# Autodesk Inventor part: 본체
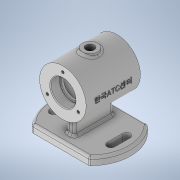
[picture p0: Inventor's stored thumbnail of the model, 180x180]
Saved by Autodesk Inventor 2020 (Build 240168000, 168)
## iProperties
Created: 2021-09
Part Number: 본체
Material: 일반
Document SubType Name: Modeling
Designer: Administrator
Density: 1 g/cm^3
Appearance: 기본값
Author: Administrator
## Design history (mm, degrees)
sketch "스케치1"
  geometry: L1 (-37.499, 0.259)-(37.499, -0.259); A1 r 52.5 centre (0, 0) between (37.752, 36.483) and (37.246, -37); 4 further points
  constraints: 4 point on circle, 2 coincident, 2 end point, 1 centre point, 1 midpoint
  dimensions: "d0" = 105 diameter of A1; "d66" = 37 vertical distance of point (-37.246, 37) point (0, 0)
extrude "돌출1" new body sketch "스케치1" stored distance "d2" = 10; taper "d3" = 0 deg
sketch "스케치2"
  geometry: L1 (35, 57)-(-35, 57); L2 (35, 57)-(35, 87); L3 (35, 87)-(-35, 87); L4 (-35, 87)-(-35, 57); 5 further points; 1 other entity
  constraints: 8 end point, 2 horizontal, 1 midpoint, 1 perpendicular, 1 vertical, 1 vertical alignment, 2 other
  dimensions: "d4" = 62 dimension on L1; "d5" = 70 distance of L1.start L1.end; "d6" = 60 diameter of L3 L1
revolve "회전1" sketch "스케치2" stored, may be unused: angle "d7" = 90 deg
revolve "회전2" stored, may be unused: angle "d19" = 90 deg
node "작업 평면1"
sketch "스케치6"
  geometry: L1 (-35, -30)-(-35, 30) reference; L2 (35, -30)-(35, 30) reference; C1 r 10 at (0, 0); 1 further point
  constraints: 1 centre point, 1 coincident
  dimensions: "d21" = 20 diameter of C1
extrude "돌출3" join sketch "스케치6" stored distance "d22" = 10; taper "d23" = 0 deg; dims "d12" = 32, "d13" = 28, "d14" = 50, "d15" = 12, "d17" = 40, "d18" = 12, "d24" = 10.917, "d26" = 4, "d27" = 2, "d29" = 29.1
sketch "스케치7"
  geometry: C1 r 10 at (0, 0) reference; 2 further points
  constraints: 1 coincident
hole "구멍1" sketch "스케치7" at (0, 0) diameter "d24" = 10.917; stored, may be unused: countersink angle "d28" = 90 deg, drill point angle "d30" = 118 deg; dims "d25" = 24, "d26" = 4, "d27" = 2, "d29" = 29.1
sketch "스케치8"
  geometry: L1 (-15, 37)-(15, 37); L2 (-10, 32)-(10, 32); L3 (10, 42)-(-10, 42); C1 r 52.5 at (0, 0) reference; A1 r 5 centre (-10, 37) between (-10, 42) and (-10, 32); A2 r 5 centre (10, 37) between (10, 32) and (10, 42); 3 further points
  constraints: 8 end point, 6 point on circle, 4 tangent, 2 centre point, 2 midpoint, 2 point on line, 1 horizontal, 1 parallel, 1 vertical alignment
  dimensions: "d31" = 20 distance of A2.centre A1.centre; "d32" = 37 distance of point (0, 0) point (0, 37); "d33" = 5 radius of A1
extrude "돌출4" cut sketch "스케치8" extent not by distance; stored distance "d34" = 0; taper "d35" = 0 deg
sketch "스케치9" dims "d36" = 46
  geometry: C1 r 16 at (0, 0) reference; 3 further points
  constraints: 1 coincident, 1 horizontal alignment, 2 other
hole "구멍2" sketch "스케치9" at (23, 0) diameter "d37" = 3.45873; stored, may be unused: countersink angle "d41" = 90 deg, drill point angle "d43" = 118 deg; dims "d38" = 8, "d39" = 4, "d40" = 2, "d42" = 10
fillet "모깎기1" dims "d47" = 0.3
fillet "모깎기2" dims "d48" = 3
fillet "모깎기3" dims "d49" = 3
chamfer "모따기1" distance "d52" = 1; stored, may be unused: second distance "d53" = 2, angle "d54" = 45 deg
node "작업 평면2"
sketch "스케치10"
  geometry: L1 (-35, 87)-(-35, 27) reference; L2 (35, 87)-(35, 27) reference; L3 (35, 87)-(-35, 87) reference; L4 (35, 27)-(-35, 27) reference; 2 further points
  constraints: 1 other
  dimensions: "d57" = 30 distance from line of L3 point (0, 57); "d58" = 35 distance from line of L1 point (0, 57)
feature "엠보싱1" sketch "스케치10" dims "d2" = 10, "d12" = 32, "d13" = 28, "d14" = 50, "d15" = 12, "d17" = 40, "d18" = 12, "d59" = 0.5, "d60" = 0
sketch "스케치11"
  geometry: L1 (15, -5)-(10, -5) reference; L2 (-52.5, -5)-(52.5, -5) reference; L3 (25, -5)-(-25, -5); L4 (-25, -5)-(-25, 29.906); L5 (-25, 29.906)-(25, 29.906); L6 (25, 29.906)-(25, -5); 4 further points
  constraints: 8 end point, 2 midpoint, 2 parallel, 1 horizontal, 1 perpendicular, 1 point on line, 1 vertical alignment
  dimensions: "d67" = 50 distance between parallel lines of L6 L4; "d68" = 34.90626 distance from line of L1.start L5
extrude "돌출5" join sketch "스케치11" stored distance "d69" = 10; taper "d70" = 0 deg
fillet "모깎기7" dims "d71" = 3
fillet "모깎기8" dims "d72" = 3
node "작업 평면3"
sketch "스케치13"
  geometry: L1 (10, -32)-(-10, -32) reference; L2 (-10, -42)-(10, -42) reference; L3 (10, 42)-(-10, 42) reference; L4 (-10, 32)-(10, 32) reference; L5 (-37.5, 36.742)-(-37.5, -36.742); L6 (37.5, 36.742)-(37.5, -36.742); L7 (0, 0)-(0, -52.5); C1 r 52.5 at (0, 0) reference; A1 r 5 centre (-10, -37) between (-10, -32) and (-10, -42) reference; A2 r 5 centre (10, -37) between (10, -42) and (10, -32) reference; A3 r 5 centre (-10, 37) between (-10, 42) and (-10, 32) reference; A4 r 5 centre (10, 37) between (10, 32) and (10, 42) reference; A5 r 52.5 centre (0, 0) between (-37.5, 36.742) and (-37.5, -36.742) reference; 5 further points
  constraints: 6 end point, 5 point on circle, 2 parallel, 2 vertical
  dimensions: "d78" = 37.5 distance from line of L5 point (0, 0); "d79" = 37.5 distance from line of L7.start L6
extrude "돌출7" cut sketch "스케치13" extent not by distance; stored distance "d80" = 0; taper "d81" = 0 deg
fillet "모깎기9" dims "d82" = 3
fillet "모깎기10" dims "d83" = 3
node "솔리드1"
mirror "미러1"
pattern_circular "원형 패턴1" dims angle "d45" = 360 deg
mirror "미러2"
sketch "스케치5"
  geometry: L1 (-35, 27)-(-35, 87) reference; L2 (35, 27)-(35, 87) reference; L3 (35, 27)-(35, 87) reference; L4 (35, 57)-(-35, 57); L5 (35, 73)-(23, 73); L6 (23, 73)-(23, 71); L7 (23, 71)-(20, 71); L8 (20, 71)-(20, 82); L9 (20, 82)-(-20, 82); L10 (-20, 82)-(-20, 71); L11 (-20, 71)-(-23, 71); L12 (-23, 71)-(-23, 73); L13 (-23, 73)-(-35, 73); 5 further points
  constraints: 20 end point, 5 perpendicular, 4 point on line, 3 midpoint, 2 horizontal, 2 parallel, 1 vertical alignment
  dimensions: "d12" = 32 diameter of L5 L4; "d13" = 28 diameter of L7 L4; "d14" = 50 diameter of L9 L4; "d15" = 12 distance of L5.start L5.end; "d17" = 40 distance of L8.end L9.end; "d18" = 12 distance of L12.end L13.end
node "투영된 루프3"
node "투영된 루프4"
node "투영된 루프5"
node "투영된 루프6"
node "투영된 루프8"
feature "A9D066F2-1C7D-4E18-AEED-F7BC21143FA4" dims "d37" = 3.45873, "d38" = 8, "d39" = 4, "d40" = 2, "d41" = 90 deg, "d42" = 10, "d43" = 118 deg
other parameters: "d20" = -95, "d56" = -48.5
